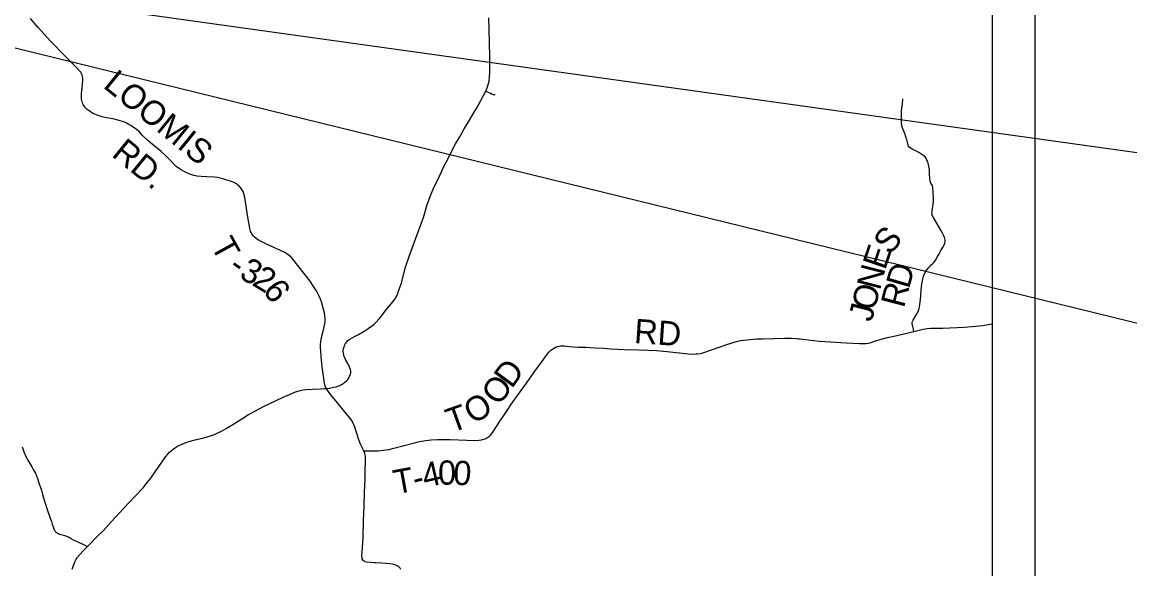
# Model space of a CAD drawing. Extents: x 0 to 34, y 0 to 22.
# Drawn here: x 6.504 to 9.099, y 15.901 to 17.181 of the extents above; entities that cross this region are included whole.
import ezdxf

# ---------------------------------------------------------------- set-up
doc = ezdxf.new("R2010")
doc.units = 0
for name, color, linetype in [('GM_X_County_Road', 7, 'Continuous'), ('GM_X_Township_Road', 7, 'Continuous'), ('GM_X_Township_Road_Text', 7, 'Continuous'), ('SH_Data', 7, 'Continuous'), ('SH_Text', 7, 'Continuous')]:
    doc.layers.add(name, color=color, linetype=linetype)

msp = doc.modelspace()

# ---------------------------------------------------------------- linework, layer by layer
at = {"layer": 'GM_X_County_Road'}
msp.add_lwpolyline([(6.6211, 15.8998), (6.6242, 15.9087), (6.6278, 15.9173), (6.631, 15.9232), (6.633, 15.9262), (6.6342, 15.9281), (6.64, 15.9355), (6.6463, 15.9424), (6.6572, 15.9533), (6.6792, 15.9754), (6.6944, 15.9909), (6.7132, 16.0114), (6.7237, 16.0229), (6.7407, 16.041), (6.7683, 16.0704), (6.7874, 16.0908), (6.7951, 16.0997), (6.8053, 16.1129), (6.816, 16.1277), (6.8335, 16.1534), (6.8409, 16.1635), (6.8448, 16.1686), (6.8496, 16.1738), (6.8534, 16.1774), (6.8577, 16.1809), (6.8632, 16.1848), (6.8682, 16.1879), (6.8765, 16.1919), (6.8861, 16.1957), (6.8949, 16.1986), (6.9128, 16.2036), (6.9296, 16.2078), (6.9457, 16.2125), (6.9544, 16.2156), (6.9629, 16.2191), (6.9713, 16.2232), (6.982, 16.2292), (6.9978, 16.239), (7.0215, 16.254), (7.0348, 16.2619), (7.0524, 16.2718), (7.0683, 16.2798), (7.1158, 16.3027), (7.1357, 16.3116), (7.1444, 16.3149), (7.1534, 16.3176), (7.1626, 16.3196), (7.1688, 16.3204), (7.1843, 16.3213), (7.2029, 16.3221), (7.211, 16.3227), (7.2163, 16.3232), (7.2245, 16.3242), (7.2336, 16.3259), (7.2396, 16.3273), (7.2454, 16.3291), (7.2483, 16.3302), (7.251, 16.3315), (7.2537, 16.3331), (7.2563, 16.3348), (7.2588, 16.3367), (7.2609, 16.3384), (7.2639, 16.3409), (7.2668, 16.3443), (7.27, 16.3491), (7.2713, 16.3517), (7.2723, 16.354), (7.2739, 16.3601), (7.2738, 16.3643), (7.2732, 16.3673), (7.2711, 16.373), (7.2672, 16.3814), (7.2628, 16.3896), (7.2599, 16.395), (7.2586, 16.3977), (7.2577, 16.4005), (7.2566, 16.4064), (7.2563, 16.4097), (7.2564, 16.4129), (7.2569, 16.4161), (7.2585, 16.4214), (7.2597, 16.4245), (7.2612, 16.4273), (7.2629, 16.43), (7.2667, 16.4346), (7.2692, 16.4369), (7.2716, 16.4388), (7.277, 16.4421), (7.2827, 16.445), (7.2861, 16.4468), (7.2918, 16.4495), (7.305, 16.4573), (7.308, 16.4591), (7.3108, 16.4608), (7.315, 16.4634), (7.3227, 16.469), (7.3277, 16.473), (7.332, 16.4771), (7.3404, 16.4859), (7.3482, 16.4954), (7.3555, 16.5054), (7.3695, 16.5223), (7.3753, 16.5297), (7.3787, 16.5347), (7.3817, 16.5399), (7.3841, 16.5455), (7.3851, 16.5484), (7.3861, 16.551), (7.389, 16.5598), (7.3926, 16.5701), (7.4014, 16.6045), (7.4115, 16.6348), (7.4353, 16.6983), (7.4447, 16.7232), (7.4533, 16.7539), (7.4616, 16.7766), (7.4685, 16.7935), (7.4765, 16.8089), (7.4863, 16.8305), (7.4905, 16.8398), (7.4963, 16.8512), (7.5041, 16.8665), (7.5124, 16.8829), (7.5196, 16.8961), (7.5255, 16.9058), (7.5295, 16.9125), (7.531, 16.9152), (7.5398, 16.9312), (7.5494, 16.9472), (7.5656, 16.9739), (7.5685, 16.9791), (7.5901, 17.0193), (7.5922, 17.0235), (7.5937, 17.0273), (7.5966, 17.0371), (7.5979, 17.0431), (7.599, 17.0522), (7.5997, 17.0646), (7.6, 17.08), (7.5997, 17.0979), (7.5986, 17.1342), (7.5978, 17.1626), (7.5975, 17.191)], dxfattribs=at)
at = {"layer": 'GM_X_Township_Road'}
for points in [[(7.2163, 16.3232), (7.2132, 16.3317), (7.2126, 16.3357), (7.2094, 16.3575), (7.2073, 16.3739), (7.2062, 16.3824), (7.2053, 16.389), (7.2043, 16.3995), (7.2036, 16.4108), (7.203, 16.4195), (7.2032, 16.4259), (7.2039, 16.4323), (7.2055, 16.4423), (7.2085, 16.4545), (7.213, 16.4742), (7.2138, 16.4803), (7.2139, 16.487), (7.2133, 16.4935), (7.2123, 16.4999), (7.211, 16.5057), (7.2095, 16.5114), (7.2052, 16.5263), (7.2031, 16.5321), (7.1993, 16.5405), (7.1936, 16.5515), (7.1886, 16.5597), (7.1786, 16.5747), (7.1675, 16.5895), (7.1384, 16.6258), (7.1341, 16.6304), (7.1295, 16.6345), (7.1245, 16.6382), (7.1192, 16.6414), (7.1081, 16.647), (7.094, 16.6534), (7.0769, 16.6608), (7.0577, 16.6708), (7.0526, 16.6743), (7.0478, 16.6782), (7.0456, 16.6804), (7.0437, 16.6828), (7.042, 16.6853), (7.0405, 16.688), (7.0393, 16.6909), (7.0384, 16.6939), (7.0366, 16.703), (7.0332, 16.7245), (7.0257, 16.7707), (7.0236, 16.7788), (7.0225, 16.7825), (7.0204, 16.7867), (7.0174, 16.7914), (7.0139, 16.7957), (7.0097, 16.7994), (7.0074, 16.8012), (7.0049, 16.8029), (7.0003, 16.8054), (6.9947, 16.8078), (6.989, 16.8097), (6.9791, 16.8126), (6.9744, 16.814), (6.9682, 16.8156), (6.9622, 16.8168), (6.9547, 16.8179), (6.9366, 16.8189), (6.9235, 16.8198), (6.9144, 16.8206), (6.9063, 16.8222), (6.8994, 16.8242), (6.8913, 16.8273), (6.8825, 16.8319), (6.877, 16.8348), (6.8706, 16.8389), (6.8652, 16.8432), (6.8585, 16.8493), (6.8498, 16.8583), (6.8392, 16.8695), (6.8301, 16.8779), (6.8241, 16.8831), (6.8094, 16.8948), (6.7982, 16.9048), (6.7865, 16.9159), (6.7788, 16.9238), (6.7724, 16.9292), (6.7644, 16.9353), (6.7585, 16.9392), (6.7529, 16.9423), (6.7479, 16.9449), (6.7415, 16.9476), (6.7316, 16.9504), (6.7196, 16.9534), (6.7116, 16.955), (6.702, 16.9569), (6.6914, 16.9595), (6.6825, 16.9624), (6.6747, 16.9654), (6.6693, 16.9678), (6.664, 16.9711), (6.6589, 16.9746), (6.6565, 16.9766), (6.6522, 16.9811), (6.6484, 16.9858), (6.6469, 16.9884), (6.6456, 16.9912), (6.6445, 16.9942), (6.6439, 16.9971), (6.6435, 17.0006), (6.6435, 17.0046), (6.6435, 17.0143), (6.6445, 17.0254), (6.6456, 17.0378), (6.646, 17.0447), (6.6461, 17.0495), (6.6458, 17.0527), (6.6452, 17.0556), (6.6442, 17.0584), (6.6431, 17.061), (6.6414, 17.0639), (6.6372, 17.0686), (6.6309, 17.0754), (6.6172, 17.089), (6.6067, 17.0995), (6.6049, 17.1013), (6.5707, 17.1366), (6.5416, 17.1681), (6.5315, 17.1798), (6.5239, 17.1896)], [(7.6123, 17.0106), (7.6099, 17.0106), (7.6084, 17.0108), (7.6069, 17.0113), (7.604, 17.0124), (7.5997, 17.0144), (7.5901, 17.0193)], [(8.6359, 16.6142), (8.6396, 16.6183), (8.6435, 16.6239), (8.6477, 16.6309), (8.6521, 16.6388), (8.6561, 16.6459), (8.6617, 16.655), (8.664, 16.6594), (8.6657, 16.6634), (8.6664, 16.6668), (8.6664, 16.6702), (8.6657, 16.6734), (8.6647, 16.6766), (8.6625, 16.6822), (8.6599, 16.6872), (8.6563, 16.694), (8.6392, 16.7234), (8.6375, 16.7263), (8.6362, 16.7288), (8.6355, 16.7313), (8.6353, 16.734), (8.6356, 16.7371), (8.6359, 16.7398), (8.638, 16.7538), (8.6389, 16.7628), (8.639, 16.7713), (8.6385, 16.7805), (8.6372, 16.7944), (8.6363, 16.7985), (8.6331, 16.8041), (8.6313, 16.809), (8.6306, 16.8138), (8.6298, 16.8268), (8.6294, 16.8358), (8.6284, 16.8426), (8.6272, 16.8479), (8.6255, 16.8536), (8.6237, 16.858), (8.6216, 16.8618), (8.6191, 16.8653), (8.616, 16.8682), (8.6115, 16.8714), (8.6048, 16.8754), (8.5972, 16.8795), (8.5903, 16.8831), (8.5845, 16.8863), (8.5821, 16.8885), (8.5806, 16.8906), (8.5794, 16.8933), (8.5786, 16.896), (8.5771, 16.9023), (8.5762, 16.9059), (8.5753, 16.9091), (8.5737, 16.9144), (8.5723, 16.9184), (8.5712, 16.9216), (8.5687, 16.9269), (8.5671, 16.9311), (8.5659, 16.9351), (8.565, 16.9402), (8.5642, 16.9457), (8.5637, 16.9522), (8.5637, 16.959), (8.5637, 16.9654), (8.5639, 16.9705), (8.5642, 16.9745), (8.5646, 16.9777), (8.5651, 16.9814), (8.566, 16.9878), (8.5674, 17.0015)], [(8.593, 16.4567), (8.5918, 16.4622), (8.5894, 16.4711), (8.5888, 16.4741), (8.5888, 16.4772), (8.5896, 16.4802), (8.591, 16.4829), (8.5991, 16.4962), (8.602, 16.5016), (8.6043, 16.5074), (8.6061, 16.5133), (8.6071, 16.5194), (8.6088, 16.5315), (8.6109, 16.562), (8.6121, 16.5712), (8.6139, 16.5801), (8.6156, 16.586), (8.618, 16.5916), (8.621, 16.597), (8.6245, 16.6021), (8.6284, 16.6068), (8.6312, 16.6099), (8.6337, 16.6124), (8.6359, 16.6142)], [(7.3047, 16.1772), (7.3292, 16.1768), (7.3384, 16.1773), (7.3507, 16.1786), (7.3629, 16.1806), (7.375, 16.1833), (7.4231, 16.1955), (7.429, 16.1973), (7.435, 16.1988), (7.4502, 16.2014), (7.4625, 16.2029), (7.4779, 16.2039), (7.4902, 16.204), (7.5057, 16.2037), (7.546, 16.2018), (7.5646, 16.2015), (7.5738, 16.2019), (7.5799, 16.2027), (7.5828, 16.2034), (7.5857, 16.2043), (7.5886, 16.2054), (7.5913, 16.2067), (7.5939, 16.2082), (7.5965, 16.2099), (7.5988, 16.2118), (7.601, 16.2139), (7.605, 16.2185), (7.6086, 16.2235), (7.6168, 16.2364), (7.6218, 16.2445), (7.6272, 16.252), (7.6325, 16.2596), (7.6422, 16.2741), (7.6491, 16.2852), (7.658, 16.2981), (7.6854, 16.3358), (7.7034, 16.3611), (7.7251, 16.3909), (7.7322, 16.401), (7.736, 16.4059), (7.738, 16.4082), (7.7403, 16.4105), (7.7427, 16.4126), (7.7452, 16.4145), (7.7479, 16.4163), (7.7535, 16.4195), (7.7564, 16.4207), (7.7593, 16.4218), (7.7624, 16.4226), (7.7655, 16.4231), (7.7687, 16.4233), (7.7749, 16.4232), (7.7859, 16.4218), (7.7954, 16.4209), (7.8066, 16.4199), (7.8245, 16.4195), (7.8459, 16.4187), (7.8662, 16.4175), (7.8834, 16.4162), (7.9147, 16.4146), (7.949, 16.4134), (7.9701, 16.4129), (7.9903, 16.4121), (8.0152, 16.4097), (8.0649, 16.4043), (8.0741, 16.4038), (8.0833, 16.4041), (8.0863, 16.4043), (8.0923, 16.4052), (8.0983, 16.4066), (8.1189, 16.4134), (8.1599, 16.4278), (8.1718, 16.4316), (8.1809, 16.434), (8.187, 16.4352), (8.2024, 16.4372), (8.2251, 16.4392), (8.2393, 16.4395), (8.2665, 16.44), (8.29, 16.4406), (8.3059, 16.4412), (8.3184, 16.4401), (8.3234, 16.4395), (8.3269, 16.4391), (8.3325, 16.4385), (8.3723, 16.434), (8.4343, 16.4302), (8.4653, 16.4285), (8.4746, 16.4284), (8.4807, 16.4288), (8.4868, 16.4296), (8.4928, 16.4309), (8.5017, 16.4336), (8.5165, 16.4383), (8.5315, 16.4425), (8.5497, 16.4468), (8.583, 16.4539), (8.593, 16.4567), (8.6057, 16.4598), (8.6147, 16.4619), (8.6239, 16.4634), (8.6331, 16.464), (8.661, 16.4644), (8.7105, 16.4667), (8.729, 16.4681), (8.7536, 16.471), (8.7763, 16.4742)], [(7.3915, 15.8996), (7.3898, 15.9021), (7.3877, 15.9044), (7.3852, 15.9063), (7.3829, 15.9078), (7.3792, 15.9096), (7.3749, 15.9109), (7.3717, 15.9116), (7.3654, 15.9125), (7.3561, 15.9134), (7.3467, 15.9141), (7.3318, 15.915), (7.3287, 15.9152), (7.312, 15.9165), (7.3079, 15.9173), (7.3058, 15.9185), (7.304, 15.9199), (7.3021, 15.922), (7.301, 15.9242), (7.3004, 15.9276), (7.3002, 15.9312), (7.3006, 15.939), (7.3016, 15.951), (7.3029, 15.974), (7.3038, 16.0141), (7.305, 16.0478), (7.3063, 16.0808), (7.3074, 16.1096), (7.3078, 16.1344), (7.3084, 16.149), (7.3086, 16.1614), (7.3083, 16.1645), (7.3078, 16.1676), (7.3072, 16.1706), (7.3062, 16.1735), (7.3047, 16.1772), (7.2975, 16.1915), (7.2949, 16.197), (7.2928, 16.2027), (7.2876, 16.2204), (7.2838, 16.2323), (7.2814, 16.2381), (7.2786, 16.2436), (7.2754, 16.249), (7.2718, 16.2541), (7.2627, 16.2655), (7.2395, 16.2933), (7.2299, 16.3054), (7.2163, 16.3232)], [(6.5042, 16.1867), (6.5083, 16.1749), (6.5131, 16.1638), (6.5176, 16.1555), (6.5222, 16.1473), (6.5269, 16.14), (6.5312, 16.1322), (6.5353, 16.1247), (6.5401, 16.1126), (6.5443, 16.0997), (6.5493, 16.0847), (6.5522, 16.0756), (6.5543, 16.0674), (6.5577, 16.0571), (6.5632, 16.0401), (6.5691, 16.0217), (6.5707, 16.0173), (6.5728, 16.0118), (6.5736, 16.0086), (6.5747, 16.0054), (6.5765, 15.9994), (6.5785, 15.9937), (6.5799, 15.9911), (6.5817, 15.9886), (6.5838, 15.9864), (6.5863, 15.9846), (6.5891, 15.9832), (6.592, 15.9821), (6.6039, 15.9788), (6.6097, 15.9768), (6.6126, 15.9755), (6.6153, 15.9741), (6.6179, 15.9724), (6.6204, 15.9705), (6.6449, 15.959), (6.6572, 15.9533)]]:
    msp.add_lwpolyline(points, dxfattribs=at)
at = {"layer": 'SH_Data'}
for p, q in [((8.8763, 21.1054), (8.8763, 14.1054)), ((8.7763, 21.0054), (8.7763, 14.2054))]:
    msp.add_line(p, q, dxfattribs=at)
at = {"layer": 'SH_Text'}
msp.add_lwpolyline([(5.3474, 17.401), (9.2222, 16.4501), (9.2222, 16.8603)], close=True, dxfattribs=at)

# ---------------------------------------------------------------- texts
at = {"layer": 'GM_X_Township_Road_Text'}
for s, height, rotation, p in [('LOOMIS', 0.05682, 320.8393, (6.6916, 17.0295)), ('RD.', 0.05682, 320.8393, (6.7116, 16.8686)), ('T', 0.0568, 299.0209, (6.9449, 16.6576)), ('S', 0.0568, 49.3822, (8.5365, 16.6339)), ('E', 0.0568, 71.0568, (8.5255, 16.5986)), ('-', 0.0568, 325.4317, (6.9845, 16.5995)), ('3', 0.0568, 332.3256, (7.0101, 16.5824)), ('2', 0.0568, 328.4106, (7.0402, 16.5666)), ('N', 0.0568, 75.5632, (8.5134, 16.5513)), ('D', 0.0568, 73.9825, (8.5813, 16.5547)), ('6', 0.0568, 307.3268, (7.066, 16.552)), ('O', 0.0568, 75.5529, (8.5009, 16.5029)), ('R', 0.0568, 75.4336, (8.5697, 16.5099)), ('J', 0.0568, 75.5579, (8.4942, 16.4771)), ('RD', 0.05682, 356.0553, (7.9366, 16.4298)), ('D', 0.0568, 53.8521, (7.651, 16.321)), ('O', 0.0568, 54.0332, (7.6217, 16.2806)), ('O', 0.0568, 30.9231, (7.5604, 16.2381)), ('T', 0.0568, 19.625, (7.5094, 16.2186)), ('T', 0.0568, 10.5333, (7.3796, 16.0752)), ('4', 0.0568, 13.2411, (7.448, 16.0899)), ('0', 0.0568, 0.9212, (7.4789, 16.0975)), ('0', 0.0568, 356.6782, (7.5128, 16.0981)), ('-', 0.0568, 14.791, (7.4258, 16.084))]:
    msp.add_text(s, height=height, rotation=rotation, dxfattribs=at).set_placement(p)

doc.saveas('drawing.dxf')
